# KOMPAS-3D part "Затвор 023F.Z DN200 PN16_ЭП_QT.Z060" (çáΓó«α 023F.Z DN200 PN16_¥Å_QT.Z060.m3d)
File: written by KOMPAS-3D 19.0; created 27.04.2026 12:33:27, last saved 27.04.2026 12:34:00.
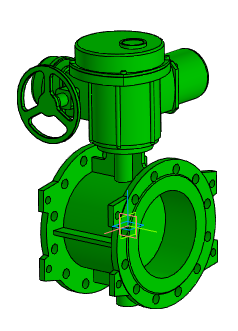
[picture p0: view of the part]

Document properties: Полное имя файла: Затвор 023F.Z DN200 PN16 + электропривод QT.Z060.a3d

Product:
- Part/product: Затвор 023F.Z DN200 PN16_ЭП_QT.Z060
    Масса: 114.51
  - Body: Тело 1
      Масса: 114.809

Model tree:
1. Операция без истории:1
